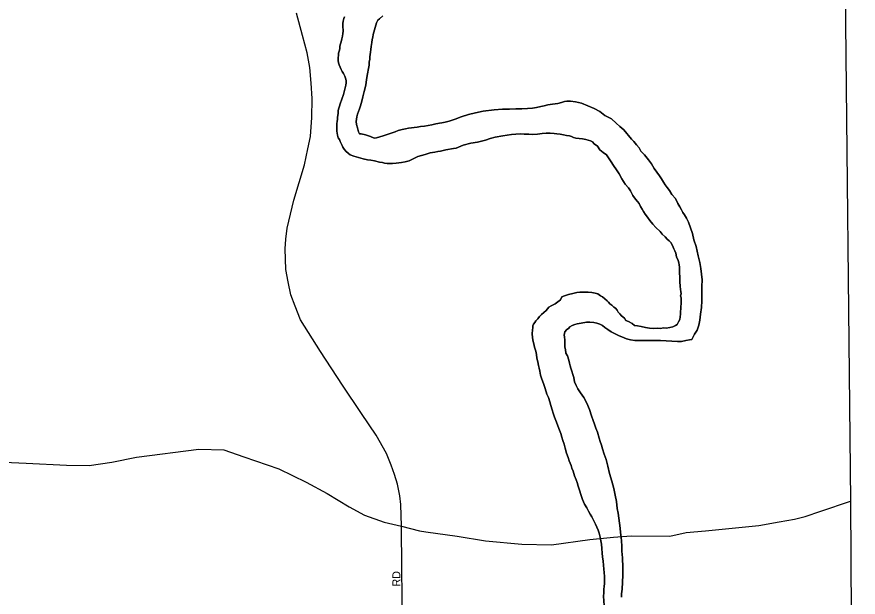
# Model space of a CAD drawing. Extents: x -561 to 1170, y 0 to 846.
# Drawn here: x 452.08 to 466.28, y 280.09 to 289.88 of the extents above; entities that cross this region are included whole.
import ezdxf

# ---------------------------------------------------------------- set-up
doc = ezdxf.new("R2010")
doc.units = 0
for name, color, linetype in [('GM_X_City_Street', 7, 'Continuous'), ('GM_X_City_Street_Text', 7, 'Continuous'), ('GM_X_County', 7, 'Continuous'), ('GM_X_Major_River', 7, 'Continuous')]:
    doc.layers.add(name, color=color, linetype=linetype)

msp = doc.modelspace()

# ---------------------------------------------------------------- linework, layer by layer
at = {"layer": 'GM_X_City_Street'}
for points in [[(458.571, 281.287), (458.561, 281.653), (458.541, 281.798), (458.501, 281.997), (458.454, 282.158), (458.396, 282.315), (458.315, 282.51), (458.144, 282.82), (457.893, 283.189), (457.573, 283.663), (457.201, 284.234), (456.867, 284.768), (456.778, 284.995), (456.704, 285.185), (456.657, 285.406), (456.621, 285.617), (456.609, 285.961), (456.621, 286.126), (456.641, 286.311), (456.755, 286.783), (456.936, 287.378), (456.991, 287.649), (457.034, 287.856), (457.044, 288.022), (457.055, 288.173), (457.06, 288.501), (457.046, 288.759), (457.025, 289.02), (456.979, 289.267), (456.9, 289.561), (456.796, 289.937)], [(448.556, 283.065), (448.664, 283.04), (449.494, 282.776), (450.062, 282.602), (450.485, 282.486), (450.718, 282.428), (451.372, 282.39), (452.237, 282.349), (452.918, 282.316), (453.302, 282.309), (453.68, 282.366), (454.101, 282.451), (455.151, 282.584), (455.574, 282.573), (455.908, 282.453), (456.499, 282.253), (456.961, 282.03), (457.318, 281.84), (457.685, 281.612), (457.947, 281.473), (458.276, 281.356), (458.571, 281.287)], [(458.981, 281.193), (459.507, 281.119), (459.986, 281.041), (460.599, 280.985), (461.1, 280.974), (461.746, 281.063), (462.146, 281.1), (462.446, 281.124), (463.1, 281.12), (463.376, 281.179), (463.702, 281.209), (464.601, 281.298), (464.941, 281.357), (465.2, 281.403), (465.383, 281.452), (465.649, 281.541), (466.148, 281.711)], [(458.571, 281.287), (458.872, 281.208), (458.981, 281.193)], [(458.577, 280.57), (458.571, 281.287)], [(457.777, 270.47), (457.876, 271.362), (458.001, 272.653), (458.167, 274.108), (458.342, 275.726), (458.552, 277.142), (458.597, 277.638), (458.616, 278.594), (458.599, 279.026), (458.58, 280.101), (458.577, 280.57)]]:
    msp.add_lwpolyline(points, dxfattribs=at)
at = {"layer": 'GM_X_County'}
msp.add_lwpolyline([(394.683, 360.045), (400.73, 360.084), (415.829, 360.183), (423.588, 360.237), (424.356, 360.246), (425.037, 360.245), (429.388, 360.259), (445.445, 360.304), (449.095, 360.314), (465.213, 360.576), (465.325, 353.501), (465.426, 347.093), (465.695, 334.098), (465.717, 328.498), (465.755, 326.068), (465.893, 314.026), (465.912, 311.201), (465.932, 307.771), (465.982, 300.221), (466.005, 296.384), (466.032, 292.559), (466.049, 290.844), (466.148, 281.711), (466.276, 259.428)], dxfattribs=at)
at = {"layer": 'GM_X_Major_River'}
for points in [[(457.609, 289.878), (457.599, 289.845), (457.583, 289.802), (457.578, 289.764), (457.578, 289.731), (457.578, 289.693), (457.584, 289.661), (457.584, 289.634), (457.579, 289.596), (457.574, 289.552), (457.564, 289.503), (457.553, 289.454), (457.543, 289.422), (457.532, 289.378), (457.527, 289.335), (457.517, 289.297), (457.506, 289.264)], [(457.506, 289.264), (457.517, 289.297), (457.527, 289.335), (457.532, 289.378), (457.543, 289.422), (457.553, 289.454), (457.564, 289.503), (457.574, 289.552), (457.579, 289.596), (457.584, 289.634), (457.584, 289.661), (457.578, 289.693), (457.578, 289.731), (457.578, 289.764), (457.583, 289.802), (457.599, 289.845), (457.609, 289.878)], [(457.81, 288.062), (457.804, 288.111), (457.809, 288.149), (457.814, 288.187), (457.83, 288.235), (457.846, 288.279), (457.861, 288.323), (457.877, 288.377), (457.898, 288.453), (457.919, 288.529), (457.94, 288.616), (457.966, 288.725), (457.982, 288.817), (457.997, 288.915), (458.013, 289.002), (458.023, 289.061), (458.023, 289.11), (458.033, 289.159), (458.038, 289.203), (458.043, 289.241), (458.048, 289.279), (458.053, 289.322), (458.058, 289.376), (458.063, 289.409), (458.068, 289.442), (458.073, 289.496), (458.084, 289.534), (458.094, 289.577), (458.136, 289.735), (458.147, 289.773), (458.173, 289.817), (458.2, 289.844), (458.254, 289.893)], [(458.254, 289.893), (458.2, 289.844), (458.173, 289.817), (458.147, 289.773), (458.136, 289.735), (458.094, 289.577), (458.084, 289.534), (458.073, 289.496), (458.068, 289.442), (458.063, 289.409), (458.058, 289.376), (458.053, 289.322), (458.048, 289.279), (458.043, 289.241), (458.038, 289.203), (458.033, 289.159), (458.023, 289.11), (458.023, 289.061), (458.013, 289.002), (457.997, 288.915), (457.982, 288.817), (457.966, 288.725), (457.94, 288.616), (457.919, 288.529), (457.898, 288.453), (457.877, 288.377), (457.861, 288.323), (457.846, 288.279), (457.83, 288.235), (457.814, 288.187), (457.809, 288.149), (457.804, 288.111), (457.81, 288.062)], [(457.506, 289.264), (457.506, 289.237), (457.501, 289.177), (457.502, 289.139), (457.508, 289.101), (457.519, 289.064), (457.535, 289.026), (457.552, 288.988), (457.569, 288.955), (457.591, 288.918), (457.613, 288.874), (457.629, 288.826), (457.635, 288.798), (457.635, 288.76), (457.63, 288.722), (457.62, 288.679), (457.609, 288.636), (457.594, 288.565), (457.535, 288.407), (457.525, 288.369), (457.509, 288.32), (457.499, 288.288), (457.499, 288.25), (457.494, 288.212), (457.489, 288.184), (457.489, 288.146), (457.484, 288.114), (457.479, 288.07), (457.479, 288.027), (457.48, 287.984), (457.48, 287.946), (457.486, 287.913), (457.491, 287.881), (457.503, 287.837), (457.525, 287.805), (457.536, 287.772), (457.552, 287.74), (457.569, 287.707), (457.58, 287.675), (457.602, 287.643), (457.629, 287.61), (457.673, 287.573), (457.706, 287.546), (457.766, 287.524), (457.842, 287.503), (457.923, 287.482), (457.994, 287.466), (458.053, 287.456), (458.113, 287.445), (458.2, 287.424), (458.249, 287.419), (458.282, 287.408), (458.33, 287.403), (458.374, 287.404), (458.417, 287.404), (458.482, 287.41), (458.569, 287.421), (458.634, 287.432), (458.699, 287.449), (458.758, 287.477), (458.844, 287.521), (458.969, 287.554), (459.055, 287.582), (459.131, 287.593), (459.185, 287.604), (459.229, 287.61), (459.321, 287.632), (459.45, 287.655), (459.494, 287.661), (459.613, 287.71), (459.742, 287.744), (459.851, 287.761), (459.921, 287.777), (459.986, 287.794), (460.067, 287.822), (460.148, 287.849), (460.278, 287.866), (460.354, 287.878), (460.424, 287.889), (460.5, 287.895), (460.57, 287.901), (460.641, 287.896), (460.717, 287.896), (460.787, 287.891), (460.863, 287.897), (460.944, 287.909), (461.009, 287.915), (461.08, 287.915), (461.145, 287.91), (461.194, 287.905), (461.248, 287.895), (461.302, 287.884), (461.357, 287.874), (461.406, 287.868), (461.438, 287.858), (461.471, 287.842), (461.514, 287.831), (461.569, 287.826), (461.623, 287.816), (461.683, 287.805), (461.721, 287.795)], [(461.721, 287.795), (461.683, 287.805), (461.623, 287.816), (461.569, 287.826), (461.514, 287.831), (461.471, 287.842), (461.438, 287.858), (461.406, 287.868), (461.357, 287.874), (461.302, 287.884), (461.248, 287.895), (461.194, 287.905), (461.145, 287.91), (461.08, 287.915), (461.009, 287.915), (460.944, 287.909), (460.863, 287.897), (460.787, 287.891), (460.717, 287.896), (460.641, 287.896), (460.57, 287.901), (460.5, 287.895), (460.424, 287.889), (460.354, 287.878), (460.278, 287.866), (460.148, 287.849), (460.067, 287.822), (459.986, 287.794), (459.921, 287.777), (459.851, 287.761), (459.742, 287.744), (459.613, 287.71), (459.494, 287.661), (459.45, 287.655), (459.321, 287.632), (459.229, 287.61), (459.185, 287.604), (459.131, 287.593), (459.055, 287.582), (458.969, 287.554), (458.844, 287.521), (458.758, 287.477), (458.699, 287.449), (458.634, 287.432), (458.569, 287.421), (458.482, 287.41), (458.417, 287.404), (458.374, 287.404), (458.33, 287.403), (458.282, 287.408), (458.249, 287.419), (458.2, 287.424), (458.113, 287.445), (458.053, 287.456), (457.994, 287.466), (457.923, 287.482), (457.842, 287.503), (457.766, 287.524), (457.706, 287.546), (457.673, 287.573), (457.629, 287.61), (457.602, 287.643), (457.58, 287.675), (457.569, 287.707), (457.552, 287.74), (457.536, 287.772), (457.525, 287.805), (457.503, 287.837), (457.491, 287.881), (457.486, 287.913), (457.48, 287.946), (457.48, 287.984), (457.479, 288.027), (457.479, 288.07), (457.484, 288.114), (457.489, 288.146), (457.489, 288.184), (457.494, 288.212), (457.499, 288.25), (457.499, 288.288), (457.509, 288.32), (457.525, 288.369), (457.535, 288.407), (457.594, 288.565), (457.609, 288.636), (457.62, 288.679), (457.63, 288.722), (457.635, 288.76), (457.635, 288.798), (457.629, 288.826), (457.613, 288.874), (457.591, 288.918), (457.569, 288.955), (457.552, 288.988), (457.535, 289.026), (457.519, 289.064), (457.508, 289.101), (457.502, 289.139), (457.501, 289.177), (457.506, 289.237), (457.506, 289.264)], [(463.607, 284.763), (463.617, 284.861), (463.632, 284.975), (463.637, 285.089), (463.641, 285.208), (463.64, 285.328), (463.645, 285.442), (463.633, 285.534), (463.621, 285.631), (463.604, 285.734), (463.576, 285.848), (463.542, 286), (463.503, 286.114), (463.48, 286.222), (463.447, 286.319), (463.414, 286.411), (463.38, 286.482), (463.347, 286.536), (463.32, 286.574), (463.293, 286.622), (463.265, 286.671), (463.232, 286.73), (463.193, 286.811), (463.133, 286.882), (463.094, 286.946), (463.051, 286.995), (463.018, 287.044), (462.99, 287.087), (462.957, 287.141), (462.924, 287.195), (462.88, 287.254), (462.836, 287.319), (462.787, 287.395), (462.737, 287.465), (462.672, 287.551), (462.611, 287.611), (462.578, 287.665), (462.535, 287.719), (462.491, 287.773), (462.452, 287.81), (462.321, 287.972), (462.255, 288.026), (462.19, 288.08), (462.113, 288.155), (462.004, 288.214), (461.917, 288.279), (461.819, 288.332), (461.716, 288.375), (461.607, 288.418), (461.504, 288.444), (461.422, 288.455), (461.362, 288.454), (461.319, 288.448), (461.271, 288.432), (461.211, 288.415), (461.119, 288.404), (461.038, 288.392), (460.978, 288.376), (460.919, 288.364), (460.848, 288.348), (460.778, 288.336), (460.697, 288.33), (460.599, 288.324), (460.502, 288.324), (460.393, 288.318), (460.274, 288.317), (460.133, 288.305), (459.949, 288.287), (459.819, 288.259), (459.7, 288.226), (459.576, 288.187), (459.473, 288.149), (459.376, 288.115), (459.306, 288.099), (459.251, 288.088), (459.214, 288.082), (459.181, 288.076), (459.149, 288.071), (459.084, 288.054), (459.019, 288.043), (458.959, 288.031), (458.889, 288.025), (458.835, 288.014), (458.786, 288.009), (458.737, 288.003), (458.688, 287.997), (458.64, 287.986), (458.58, 287.975), (458.515, 287.958), (458.461, 287.936), (458.261, 287.869), (458.207, 287.853), (458.148, 287.836), (458.11, 287.83), (458.045, 287.857), (457.963, 287.884), (457.892, 287.9), (457.86, 287.905), (457.843, 287.937), (457.826, 288.002), (457.81, 288.062)], [(457.81, 288.062), (457.826, 288.002), (457.843, 287.937), (457.86, 287.905), (457.892, 287.9), (457.963, 287.884), (458.045, 287.857), (458.11, 287.83), (458.148, 287.836), (458.207, 287.853), (458.261, 287.869), (458.461, 287.936), (458.515, 287.958), (458.58, 287.975), (458.64, 287.986), (458.688, 287.997), (458.737, 288.003), (458.786, 288.009), (458.835, 288.014), (458.889, 288.025), (458.959, 288.031), (459.019, 288.043), (459.084, 288.054), (459.149, 288.071), (459.181, 288.076), (459.214, 288.082), (459.251, 288.088), (459.306, 288.099), (459.376, 288.115), (459.473, 288.149), (459.576, 288.187), (459.7, 288.226), (459.819, 288.259), (459.949, 288.287), (460.133, 288.305), (460.274, 288.317), (460.393, 288.318), (460.502, 288.324), (460.599, 288.324), (460.697, 288.33), (460.778, 288.336), (460.848, 288.348), (460.919, 288.364), (460.978, 288.376), (461.038, 288.392), (461.119, 288.404), (461.211, 288.415), (461.271, 288.432), (461.319, 288.448), (461.362, 288.454), (461.422, 288.455), (461.504, 288.444), (461.607, 288.418), (461.716, 288.375), (461.819, 288.332), (461.917, 288.279), (462.004, 288.214), (462.113, 288.155), (462.19, 288.08), (462.255, 288.026), (462.321, 287.972), (462.452, 287.81), (462.491, 287.773), (462.535, 287.719), (462.578, 287.665), (462.611, 287.611), (462.672, 287.551), (462.737, 287.465), (462.787, 287.395), (462.836, 287.319), (462.88, 287.254), (462.924, 287.195), (462.957, 287.141), (462.99, 287.087), (463.018, 287.044), (463.051, 286.995), (463.094, 286.946), (463.133, 286.882), (463.193, 286.811), (463.232, 286.73), (463.265, 286.671), (463.293, 286.622), (463.32, 286.574), (463.347, 286.536), (463.38, 286.482), (463.414, 286.411), (463.447, 286.319), (463.48, 286.222), (463.503, 286.114), (463.542, 286), (463.576, 285.848), (463.604, 285.734), (463.621, 285.631), (463.633, 285.534), (463.645, 285.442), (463.64, 285.328), (463.641, 285.208), (463.637, 285.089), (463.632, 284.975), (463.617, 284.861), (463.607, 284.763)], [(461.721, 287.795), (461.759, 287.784), (461.791, 287.768), (461.819, 287.736), (461.879, 287.693), (461.917, 287.633), (461.972, 287.59), (462.027, 287.547), (462.109, 287.428), (462.147, 287.369), (462.197, 287.293), (462.241, 287.228), (462.29, 287.142), (462.345, 287.055), (462.4, 286.991), (462.433, 286.942), (462.472, 286.861), (462.521, 286.802), (462.554, 286.764), (462.581, 286.726), (462.603, 286.677), (462.631, 286.634), (462.653, 286.591), (462.681, 286.548), (462.719, 286.499), (462.763, 286.44), (462.812, 286.38), (462.861, 286.321), (462.933, 286.256), (462.971, 286.208), (463.02, 286.165), (463.053, 286.127), (463.086, 286.1), (463.113, 286.068), (463.135, 286.03), (463.157, 285.992), (463.168, 285.965), (463.185, 285.932), (463.201, 285.889), (463.213, 285.83), (463.24, 285.765), (463.252, 285.727), (463.257, 285.694), (463.263, 285.656), (463.263, 285.618), (463.264, 285.559), (463.265, 285.483), (463.265, 285.407), (463.271, 285.331), (463.277, 285.277), (463.283, 285.244), (463.289, 285.206), (463.278, 285.173), (463.289, 285.136), (463.29, 285.098), (463.29, 285.065), (463.29, 285.032), (463.285, 284.994), (463.276, 284.859), (463.266, 284.772), (463.244, 284.734), (463.223, 284.69), (463.196, 284.668), (463.147, 284.646), (463.099, 284.635), (463.039, 284.624), (462.985, 284.629), (462.947, 284.618), (462.882, 284.623), (462.817, 284.622), (462.757, 284.627), (462.687, 284.638), (462.616, 284.654), (462.551, 284.664), (462.502, 284.669), (462.464, 284.702), (462.398, 284.739), (462.355, 284.755), (462.333, 284.793), (462.284, 284.836), (462.256, 284.868), (462.229, 284.895), (462.207, 284.928), (462.18, 284.96), (462.152, 284.982), (462.119, 285.014), (462.087, 285.035), (462.065, 285.062), (462.038, 285.089), (461.999, 285.122), (461.961, 285.154), (461.928, 285.17), (461.885, 285.202), (461.836, 285.218), (461.781, 285.229), (461.722, 285.234), (461.581, 285.233), (461.527, 285.227), (461.462, 285.21), (461.386, 285.194), (461.321, 285.171)], [(461.321, 285.171), (461.386, 285.194), (461.462, 285.21), (461.527, 285.227), (461.581, 285.233), (461.722, 285.234), (461.781, 285.229), (461.836, 285.218), (461.885, 285.202), (461.928, 285.17), (461.961, 285.154), (461.999, 285.122), (462.038, 285.089), (462.065, 285.062), (462.087, 285.035), (462.119, 285.014), (462.152, 284.982), (462.18, 284.96), (462.207, 284.928), (462.229, 284.895), (462.256, 284.868), (462.284, 284.836), (462.333, 284.793), (462.355, 284.755), (462.398, 284.739), (462.464, 284.702), (462.502, 284.669), (462.551, 284.664), (462.616, 284.654), (462.687, 284.638), (462.757, 284.627), (462.817, 284.622), (462.882, 284.623), (462.947, 284.618), (462.985, 284.629), (463.039, 284.624), (463.099, 284.635), (463.147, 284.646), (463.196, 284.668), (463.223, 284.69), (463.244, 284.734), (463.266, 284.772), (463.276, 284.859), (463.285, 284.994), (463.29, 285.032), (463.29, 285.065), (463.29, 285.098), (463.289, 285.136), (463.278, 285.173), (463.289, 285.206), (463.283, 285.244), (463.277, 285.277), (463.271, 285.331), (463.265, 285.407), (463.265, 285.483), (463.264, 285.559), (463.263, 285.618), (463.263, 285.656), (463.257, 285.694), (463.252, 285.727), (463.24, 285.765), (463.213, 285.83), (463.201, 285.889), (463.185, 285.932), (463.168, 285.965), (463.157, 285.992), (463.135, 286.03), (463.113, 286.068), (463.086, 286.1), (463.053, 286.127), (463.02, 286.165), (462.971, 286.208), (462.933, 286.256), (462.861, 286.321), (462.812, 286.38), (462.763, 286.44), (462.719, 286.499), (462.681, 286.548), (462.653, 286.591), (462.631, 286.634), (462.603, 286.677), (462.581, 286.726), (462.554, 286.764), (462.521, 286.802), (462.472, 286.861), (462.433, 286.942), (462.4, 286.991), (462.345, 287.055), (462.29, 287.142), (462.241, 287.228), (462.197, 287.293), (462.147, 287.369), (462.109, 287.428), (462.027, 287.547), (461.972, 287.59), (461.917, 287.633), (461.879, 287.693), (461.819, 287.736), (461.791, 287.768), (461.759, 287.784), (461.721, 287.795)], [(461.321, 285.171), (461.278, 285.155), (461.251, 285.106), (461.165, 285.035), (461.095, 285.002), (461.057, 284.98), (461.009, 284.925), (460.971, 284.887), (460.934, 284.854), (460.901, 284.821), (460.869, 284.783), (460.837, 284.75), (460.821, 284.723), (460.8, 284.691), (460.789, 284.663), (460.784, 284.636), (460.779, 284.593), (460.774, 284.533), (460.78, 284.462), (460.791, 284.403), (460.803, 284.36), (460.814, 284.305), (460.836, 284.235), (460.847, 284.181), (460.853, 284.121), (460.87, 284.056), (460.882, 283.997), (460.893, 283.953), (460.904, 283.899), (460.916, 283.834), (460.938, 283.764), (460.966, 283.693), (460.994, 283.607), (461.021, 283.515), (461.049, 283.455), (461.071, 283.385), (461.088, 283.32), (461.111, 283.249), (461.127, 283.19), (461.15, 283.125), (461.172, 283.071), (461.238, 282.903), (461.26, 282.849), (461.277, 282.789), (461.294, 282.73), (461.316, 282.67), (461.333, 282.6), (461.356, 282.519), (461.383, 282.443), (461.4, 282.389), (461.417, 282.351), (461.433, 282.307), (461.445, 282.264), (461.467, 282.215), (461.489, 282.134), (461.517, 282.069), (461.534, 282.021), (461.55, 281.961), (461.573, 281.891), (461.595, 281.82), (461.623, 281.739), (461.661, 281.658), (461.695, 281.593), (461.728, 281.539), (461.755, 281.49), (461.783, 281.442), (461.816, 281.377), (461.843, 281.323), (461.865, 281.269), (461.888, 281.22), (461.904, 281.171), (461.921, 281.101), (461.933, 281.041), (461.944, 280.982), (461.95, 280.911), (461.956, 280.83), (461.962, 280.77), (461.974, 280.694), (461.98, 280.629), (461.986, 280.564), (461.992, 280.504), (461.998, 280.439), (461.998, 280.38), (461.993, 280.353), (461.993, 280.315), (461.988, 280.277), (461.983, 280.217), (461.984, 280.163), (461.979, 280.108), (461.991, 279.951)], [(461.991, 279.951), (461.979, 280.108), (461.984, 280.163), (461.983, 280.217), (461.988, 280.277), (461.993, 280.315), (461.993, 280.353), (461.998, 280.38), (461.998, 280.439), (461.992, 280.504), (461.986, 280.564), (461.98, 280.629), (461.974, 280.694), (461.962, 280.77), (461.956, 280.83), (461.95, 280.911), (461.944, 280.982), (461.933, 281.041), (461.921, 281.101), (461.904, 281.171), (461.888, 281.22), (461.865, 281.269), (461.843, 281.323), (461.816, 281.377), (461.783, 281.442), (461.755, 281.49), (461.728, 281.539), (461.695, 281.593), (461.661, 281.658), (461.623, 281.739), (461.595, 281.82), (461.573, 281.891), (461.55, 281.961), (461.534, 282.021), (461.517, 282.069), (461.489, 282.134), (461.467, 282.215), (461.445, 282.264), (461.433, 282.307), (461.417, 282.351), (461.4, 282.389), (461.383, 282.443), (461.356, 282.519), (461.333, 282.6), (461.316, 282.67), (461.294, 282.73), (461.277, 282.789), (461.26, 282.849), (461.238, 282.903), (461.172, 283.071), (461.15, 283.125), (461.127, 283.19), (461.111, 283.249), (461.088, 283.32), (461.071, 283.385), (461.049, 283.455), (461.021, 283.515), (460.994, 283.607), (460.966, 283.693), (460.938, 283.764), (460.916, 283.834), (460.904, 283.899), (460.893, 283.953), (460.882, 283.997), (460.87, 284.056), (460.853, 284.121), (460.847, 284.181), (460.836, 284.235), (460.814, 284.305), (460.803, 284.36), (460.791, 284.403), (460.78, 284.462), (460.774, 284.533), (460.779, 284.593), (460.784, 284.636), (460.789, 284.663), (460.8, 284.691), (460.821, 284.723), (460.837, 284.75), (460.869, 284.783), (460.901, 284.821), (460.934, 284.854), (460.971, 284.887), (461.009, 284.925), (461.057, 284.98), (461.095, 285.002), (461.165, 285.035), (461.251, 285.106), (461.278, 285.155), (461.321, 285.171)], [(462.283, 280.089), (462.282, 280.143), (462.292, 280.224), (462.302, 280.344), (462.306, 280.463), (462.305, 280.588), (462.298, 280.751), (462.286, 280.864), (462.291, 280.957), (462.285, 281.033), (462.279, 281.103), (462.267, 281.179), (462.261, 281.255), (462.25, 281.336), (462.238, 281.423), (462.227, 281.504), (462.21, 281.586), (462.198, 281.705), (462.175, 281.808), (462.152, 281.922), (462.119, 282.046), (462.08, 282.176), (462.051, 282.301), (462.023, 282.409), (461.99, 282.501), (461.962, 282.588), (461.945, 282.653), (461.923, 282.712), (461.906, 282.772), (461.878, 282.869), (461.851, 282.94), (461.828, 283.005), (461.806, 283.069), (461.778, 283.145), (461.745, 283.254), (461.695, 283.362), (461.645, 283.454), (461.591, 283.535), (461.547, 283.605), (461.519, 283.659), (461.491, 283.718), (461.48, 283.794), (461.43, 283.951), (461.418, 283.989), (461.407, 284.033), (461.396, 284.087), (461.374, 284.157), (461.346, 284.206), (461.335, 284.265), (461.329, 284.303), (461.328, 284.352), (461.328, 284.423), (461.322, 284.477), (461.316, 284.509), (461.327, 284.564), (461.359, 284.602), (461.386, 284.618), (461.413, 284.646), (461.45, 284.673), (461.494, 284.69), (461.537, 284.701), (461.602, 284.712), (461.694, 284.724), (461.748, 284.724), (461.813, 284.719), (461.867, 284.708), (461.916, 284.692), (461.96, 284.671), (462.004, 284.639), (462.053, 284.601), (462.107, 284.563), (462.167, 284.537), (462.211, 284.515), (462.243, 284.494), (462.287, 284.478), (462.325, 284.462), (462.369, 284.446), (462.434, 284.43), (462.51, 284.42), (462.586, 284.415), (462.656, 284.415), (462.727, 284.416), (462.786, 284.416), (462.862, 284.417), (462.943, 284.417), (463.225, 284.403), (463.296, 284.403), (463.366, 284.42), (463.431, 284.431), (463.469, 284.437), (463.512, 284.524), (463.56, 284.589), (463.586, 284.676), (463.607, 284.763)], [(463.607, 284.763), (463.586, 284.676), (463.56, 284.589), (463.512, 284.524), (463.469, 284.437), (463.431, 284.431), (463.366, 284.42), (463.296, 284.403), (463.225, 284.403), (462.943, 284.417), (462.862, 284.417), (462.786, 284.416), (462.727, 284.416), (462.656, 284.415), (462.586, 284.415), (462.51, 284.42), (462.434, 284.43), (462.369, 284.446), (462.325, 284.462), (462.287, 284.478), (462.243, 284.494), (462.211, 284.515), (462.167, 284.537), (462.107, 284.563), (462.053, 284.601), (462.004, 284.639), (461.96, 284.671), (461.916, 284.692), (461.867, 284.708), (461.813, 284.719), (461.748, 284.724), (461.694, 284.724), (461.602, 284.712), (461.537, 284.701), (461.494, 284.69), (461.45, 284.673), (461.413, 284.646), (461.386, 284.618), (461.359, 284.602), (461.327, 284.564), (461.316, 284.509), (461.322, 284.477), (461.328, 284.423), (461.328, 284.352), (461.329, 284.303), (461.335, 284.265), (461.346, 284.206), (461.374, 284.157), (461.396, 284.087), (461.407, 284.033), (461.418, 283.989), (461.43, 283.951), (461.48, 283.794), (461.491, 283.718), (461.519, 283.659), (461.547, 283.605), (461.591, 283.535), (461.645, 283.454), (461.695, 283.362), (461.745, 283.254), (461.778, 283.145), (461.806, 283.069), (461.828, 283.005), (461.851, 282.94), (461.878, 282.869), (461.906, 282.772), (461.923, 282.712), (461.945, 282.653), (461.962, 282.588), (461.99, 282.501), (462.023, 282.409), (462.051, 282.301), (462.08, 282.176), (462.119, 282.046), (462.152, 281.922), (462.175, 281.808), (462.198, 281.705), (462.21, 281.586), (462.227, 281.504), (462.238, 281.423), (462.25, 281.336), (462.261, 281.255), (462.267, 281.179), (462.279, 281.103), (462.285, 281.033), (462.291, 280.957), (462.286, 280.864), (462.298, 280.751), (462.305, 280.588), (462.306, 280.463), (462.302, 280.344), (462.292, 280.224), (462.282, 280.143), (462.283, 280.089)]]:
    msp.add_lwpolyline(points, dxfattribs=at)

# ---------------------------------------------------------------- texts
at = {"layer": 'GM_X_City_Street_Text'}
msp.add_text('RD', height=0.135, rotation=90, dxfattribs=at).set_placement((458.551, 280.269))

doc.saveas('drawing.dxf')
